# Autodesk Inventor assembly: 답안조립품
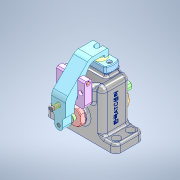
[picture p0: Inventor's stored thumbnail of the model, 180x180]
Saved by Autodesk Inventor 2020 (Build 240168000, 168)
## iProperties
Created: 2023-12
Part Number: 답안조립품
Document SubType Name: Assembly
Designer: oem
Author: oem
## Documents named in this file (14)
- C:\Users\oem\Desktop\731208V1014\답안조립품.iam
- C:\Users\oem\Desktop\731208V1014\본체.ipt
- C:\Users\oem\Desktop\731208V1014\가이드 부시.ipt
- C:\Users\oem\Desktop\731208V1014\조절 부시.ipt
- C:\Users\oem\Desktop\731208V1014\클램프 샤프트.ipt
- C:\Users\oem\Desktop\731208V1014\고정대.ipt
- C:\Users\oem\Desktop\731208V1014\육각 소켓 머리 볼트 M3 x 8.ipt
- C:\Users\oem\Desktop\731208V1014\가공품.ipt
- C:\Users\oem\Desktop\731208V1014\브라켓.ipt
- C:\Users\oem\Desktop\731208V1014\클램프.ipt
- C:\Users\oem\Desktop\731208V1014\육각 머리 볼트 M6 x 12.ipt
- C:\Users\oem\Desktop\731208V1014\육각 소켓 머리 볼트 M3 x 30.ipt
- C:\Users\oem\Desktop\731208V1014\스프링.ipt
- C:\Users\oem\Desktop\731208V1014\핀.ipt
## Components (4 placed, 4 different names)
1. 가이드 부시:1
2. 고정대:1
3. 가공품:1
4. 핀:1 — 플러쉬:2
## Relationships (1: Flush 1)
- 플러쉬:2 [Flush]: 핀:1
